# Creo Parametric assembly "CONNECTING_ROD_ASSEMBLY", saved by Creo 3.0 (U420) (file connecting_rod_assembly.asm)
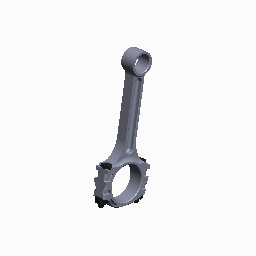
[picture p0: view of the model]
Units: millimeter Kilogram Sec (mmKs); MM, KILOGRAM, SECS

Created from: INLBS_ASM_DESIGN.ASM

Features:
  1. datum plane "ASM_RIGHT"
  2. datum plane "ASM_TOP"
  3. datum plane "ASM_FRONT"
  4. coordinate system
  5. component "CONNECTING_ROD_ASSEMBLY_SW"
  6. datum plane "ADTM3"
  7. component "BOLT_NUT_ASSEMBLY"
  8. datum plane "ADTM4"
  9. component "BOLT_NUT_ASSEMBLY"

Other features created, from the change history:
  component interface "INTFC001"
  component "BOLT_NUT_ASSEMBLY.ASM"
